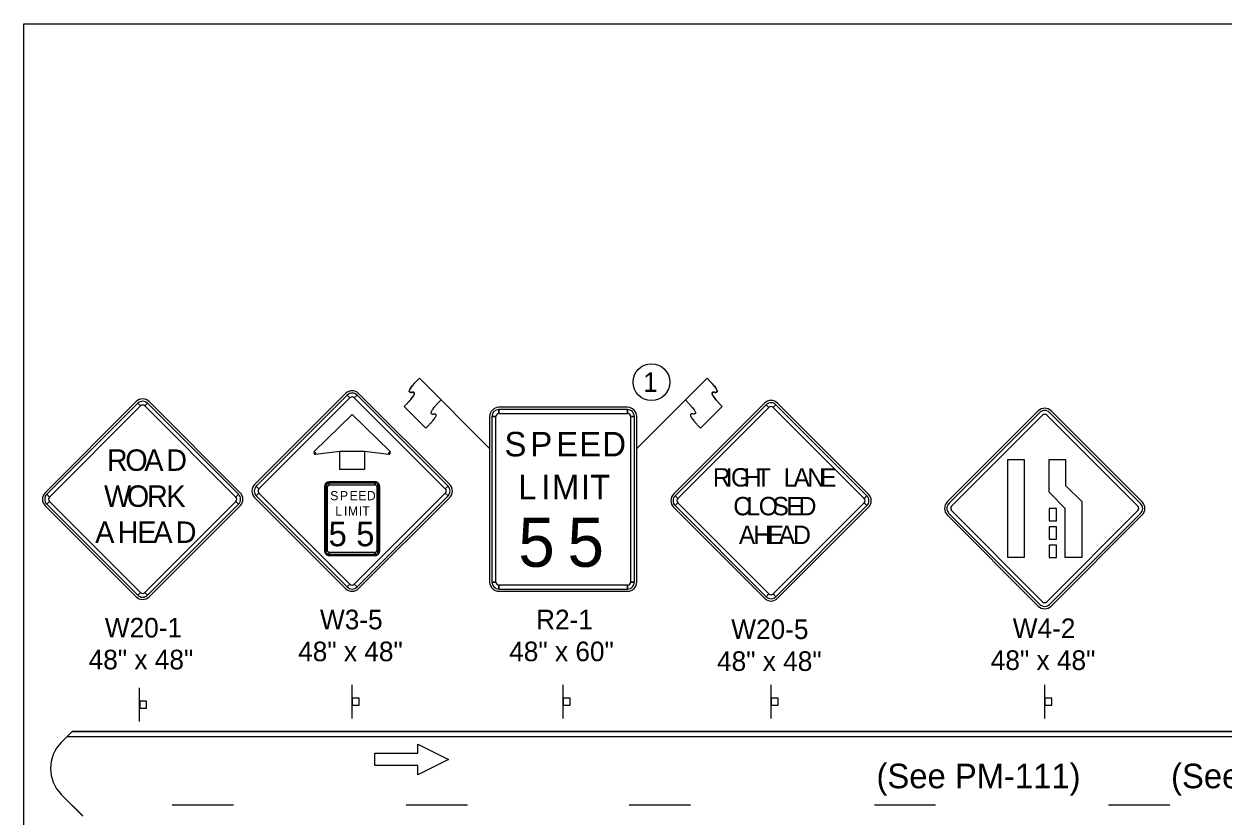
# Model space of a CAD drawing. Extents: x 10133 to 2270741, y 5363 to 1733450.
# Drawn here: x 28133 to 29111, y 9298 to 9944 of the extents above; entities that cross this region are included whole.
import ezdxf

# ---------------------------------------------------------------- set-up
doc = ezdxf.new("R2010")
doc.units = 0
for name, color, linetype in [('dsnNonPlotable', 7, 'Continuous'), ('dsnShtPlotShapeBatchPrint', 7, 'Continuous'), ('dsnStdBorder', 7, 'Continuous'), ('Level 2', 7, 'Continuous'), ('SheetBorder', 7, 'Continuous'), ('SheetText', 7, 'Continuous')]:
    doc.layers.add(name, color=color, linetype=linetype)

msp = doc.modelspace()

# ---------------------------------------------------------------- linework, layer by layer
at = {"layer": 'dsnNonPlotable'}
for p, q in [((28171.75, 9367.06), (28162.96, 9358.27)), ((28162.96, 9315.85), (28180.53, 9298.29))]:
    msp.add_line(p, q, dxfattribs=at)
msp.add_lwpolyline([(28167.75, 9363.06), (30246.68, 9363.06)], dxfattribs=at)
msp.add_arc((28184.17, 9337.07), 30, 135, 225, dxfattribs=at)
at = {"layer": 'dsnShtPlotShapeBatchPrint'}
msp.add_circle((28644.37, 9652.02), 15, dxfattribs=at)
at = {"layer": 'dsnStdBorder'}
for p, q in [((28512.42, 9597.93), (28455.1, 9655.24)), ((28455.1, 9655.24), (28472.79, 9637.56)), ((28632.42, 9597.93), (28689.74, 9655.24)), ((28689.74, 9655.24), (28672.06, 9637.56)), ((28224.04, 9636.12), (28149.79, 9561.87)), ((28308.89, 9561.87), (28234.64, 9636.12)), ((28394.94, 9642.77), (28320.7, 9568.53)), ((28396.27, 9641.45), (28398.48, 9639.24)), ((28402.02, 9639.24), (28404.23, 9641.45)), ((28479.8, 9568.53), (28405.55, 9642.77)), ((28225.36, 9634.8), (28227.57, 9632.59)), ((28231.11, 9632.59), (28233.32, 9634.8)), ((28442.73, 9632.25), (28460.4, 9614.57)), ((28460.4, 9614.57), (28442.73, 9632.25)), ((28624.92, 9631.48), (28519.92, 9631.48)), ((28519.92, 9626.48), (28519.92, 9629.6)), ((28624.92, 9629.6), (28624.92, 9626.48)), ((28736.67, 9634.87), (28662.42, 9560.62)), ((28702.12, 9632.25), (28684.44, 9614.57)), ((28684.44, 9614.57), (28702.12, 9632.25)), ((28737.99, 9633.54), (28740.2, 9631.33)), ((28743.74, 9631.33), (28745.95, 9633.54)), ((28821.52, 9560.62), (28747.27, 9634.87)), ((28959.97, 9628.56), (28885.72, 9554.31)), ((28885.72, 9554.31), (28959.97, 9628.56)), ((28961.3, 9627.23), (28887.05, 9552.99)), ((29043.5, 9552.99), (28969.25, 9627.23)), ((29044.83, 9554.31), (28970.58, 9628.56)), ((28970.58, 9628.56), (29044.83, 9554.31)), ((28970.58, 9628.56), (28970.58, 9628.56)), ((28512.42, 9623.98), (28512.42, 9488.98)), ((28514.3, 9623.98), (28517.42, 9623.98)), ((28627.42, 9623.98), (28630.55, 9623.98)), ((28632.42, 9488.98), (28632.42, 9623.98)), ((28889.26, 9550.78), (28963.51, 9625.02)), ((28967.04, 9625.02), (28967.04, 9625.03)), ((28967.04, 9625.02), (29041.29, 9550.78)), ((28370.25, 9594.47), (28369.36, 9595.36)), ((28370.4, 9593.23), (28370.25, 9594.47)), ((28430.25, 9594.47), (28430.09, 9593.23)), ((28431.13, 9595.36), (28430.25, 9594.47)), ((28324.23, 9564.99), (28322.02, 9567.2)), ((28377.75, 9566.97), (28377.75, 9514.47)), ((28378.69, 9566.97), (28380.25, 9566.97)), ((28419, 9570.72), (28381.5, 9570.72)), ((28381.5, 9568.22), (28381.5, 9569.78)), ((28419, 9569.78), (28419, 9568.22)), ((28420.25, 9566.97), (28421.81, 9566.97)), ((28422.75, 9514.47), (28422.75, 9566.97)), ((28478.47, 9567.2), (28476.26, 9564.99)), ((28153.33, 9558.34), (28151.12, 9560.55)), ((28307.56, 9560.55), (28305.36, 9558.34)), ((28320.7, 9557.92), (28394.94, 9483.67)), ((28322.02, 9559.24), (28324.23, 9561.45)), ((28405.55, 9483.67), (28479.8, 9557.92)), ((28476.26, 9561.45), (28478.47, 9559.24)), ((28665.96, 9557.08), (28663.75, 9559.29)), ((28820.19, 9559.29), (28817.98, 9557.08)), ((28149.79, 9551.27), (28224.04, 9477.02)), ((28151.12, 9552.59), (28153.33, 9554.8)), ((28234.64, 9477.02), (28308.89, 9551.27)), ((28305.36, 9554.8), (28307.56, 9552.59)), ((28662.42, 9550.01), (28736.67, 9475.77)), ((28663.75, 9551.34), (28665.96, 9553.55)), ((28747.27, 9475.77), (28821.52, 9550.01)), ((28817.98, 9553.55), (28820.19, 9551.34)), ((28963.51, 9472.99), (28889.26, 9547.24)), ((29041.29, 9547.24), (28967.04, 9472.99)), ((28885.72, 9543.71), (28959.97, 9469.46)), ((28959.97, 9469.46), (28885.72, 9543.71)), ((28887.05, 9545.03), (28961.3, 9470.78)), ((28969.25, 9470.78), (29043.5, 9545.03)), ((28970.58, 9469.46), (29044.83, 9543.71)), ((29044.83, 9543.71), (28970.58, 9469.46)), ((28380.25, 9514.47), (28378.69, 9514.47)), ((28381.5, 9511.66), (28381.5, 9513.22)), ((28381.5, 9510.72), (28419, 9510.72)), ((28419, 9513.22), (28419, 9511.66)), ((28421.81, 9514.47), (28420.25, 9514.47)), ((28517.42, 9488.98), (28514.3, 9488.98)), ((28630.55, 9488.98), (28627.42, 9488.98)), ((28227.57, 9480.56), (28225.36, 9478.35)), ((28233.32, 9478.35), (28231.11, 9480.56)), ((28398.48, 9487.21), (28396.27, 9485)), ((28404.23, 9485), (28402.02, 9487.21)), ((28519.92, 9483.35), (28519.92, 9486.48)), ((28519.92, 9481.48), (28624.92, 9481.48)), ((28624.92, 9486.48), (28624.92, 9483.35)), ((28740.2, 9479.3), (28737.99, 9477.09)), ((28745.95, 9477.09), (28743.74, 9479.3))]:
    msp.add_line(p, q, dxfattribs=at)
for points in [[(28396.27, 9641.45), (28322.02, 9567.2), (28324.23, 9564.99), (28398.48, 9639.24), (28396.27, 9641.45)], [(28478.47, 9567.2), (28404.23, 9641.45), (28402.02, 9639.24), (28476.26, 9564.99), (28478.47, 9567.2)], [(28225.36, 9634.8), (28151.12, 9560.55), (28153.33, 9558.34), (28227.57, 9632.59), (28225.36, 9634.8)], [(28307.56, 9560.55), (28233.32, 9634.8), (28231.11, 9632.59), (28305.36, 9558.34), (28307.56, 9560.55)], [(28400.25, 9625.72), (28369.36, 9595.36), (28370.25, 9594.47), (28370.4, 9593.23), (28390.25, 9595.72), (28410.25, 9595.72), (28430.09, 9593.23), (28430.25, 9594.47), (28431.13, 9595.36), (28400.25, 9625.72)], [(28624.92, 9629.6), (28519.92, 9629.6), (28519.92, 9626.48), (28624.92, 9626.48), (28624.92, 9629.6)], [(28737.99, 9633.54), (28663.75, 9559.29), (28665.96, 9557.08), (28740.2, 9631.33), (28737.99, 9633.54)], [(28820.19, 9559.29), (28745.95, 9633.54), (28743.74, 9631.33), (28817.98, 9557.08), (28820.19, 9559.29)], [(28514.3, 9623.98), (28514.3, 9488.98), (28517.42, 9488.98), (28517.42, 9623.98), (28514.3, 9623.98)], [(28630.55, 9488.98), (28630.55, 9623.98), (28627.42, 9623.98), (28627.42, 9488.98), (28630.55, 9488.98)], [(28410.25, 9580.72), (28390.25, 9580.72), (28390.25, 9595.72), (28410.25, 9595.72), (28410.25, 9580.72)], [(28948.52, 9589.01), (28948.52, 9509.01), (28935.02, 9509.01), (28935.02, 9589.01)], [(28982.28, 9567.85), (28995.53, 9554.6), (28995.53, 9509.01), (28982.03, 9509.01), (28982.03, 9549.01), (28968.78, 9562.26), (28968.78, 9589.01), (28982.28, 9589.01)], [(28378.69, 9566.97), (28378.69, 9514.47), (28380.25, 9514.47), (28380.25, 9566.97), (28378.69, 9566.97)], [(28419, 9569.78), (28381.5, 9569.78), (28381.5, 9568.22), (28419, 9568.22), (28419, 9569.78)], [(28421.81, 9514.47), (28421.81, 9566.97), (28420.25, 9566.97), (28420.25, 9514.47), (28421.81, 9514.47)], [(28322.02, 9559.24), (28396.27, 9485), (28398.48, 9487.21), (28324.23, 9561.45), (28322.02, 9559.24)], [(28404.23, 9485), (28478.47, 9559.24), (28476.26, 9561.45), (28402.02, 9487.21), (28404.23, 9485)], [(28151.12, 9552.59), (28225.36, 9478.35), (28227.57, 9480.56), (28153.33, 9554.8), (28151.12, 9552.59)], [(28233.32, 9478.35), (28307.56, 9552.59), (28305.36, 9554.8), (28231.11, 9480.56), (28233.32, 9478.35)], [(28663.75, 9551.34), (28737.99, 9477.09), (28740.2, 9479.3), (28665.96, 9553.55), (28663.75, 9551.34)], [(28745.95, 9477.09), (28820.19, 9551.34), (28817.98, 9553.55), (28743.74, 9479.3), (28745.95, 9477.09)], [(28974.78, 9549.01), (28968.78, 9549.01), (28968.78, 9539.01), (28974.78, 9539.01)], [(28974.78, 9534.01), (28968.78, 9534.01), (28968.78, 9524.01), (28974.78, 9524.01)], [(28974.78, 9519.01), (28968.78, 9519.01), (28968.78, 9509.01), (28974.78, 9509.01)], [(28381.5, 9511.66), (28419, 9511.66), (28419, 9513.22), (28381.5, 9513.22), (28381.5, 9511.66)], [(28519.92, 9483.35), (28624.92, 9483.35), (28624.92, 9486.48), (28519.92, 9486.48), (28519.92, 9483.35)]]:
    msp.add_lwpolyline(points, close=True, dxfattribs=at)
for points in [[(28887.05, 9552.99), (28961.3, 9627.23)], [(28969.25, 9627.23), (29043.5, 9552.99)], [(28889.26, 9550.78), (28963.51, 9625.03)], [(28967.04, 9625.03), (29041.29, 9550.78)], [(28963.51, 9472.99), (28889.26, 9547.24)], [(29041.29, 9547.24), (28967.04, 9472.99)], [(28961.3, 9470.78), (28887.05, 9545.03)], [(29043.5, 9545.03), (28969.25, 9470.78)]]:
    msp.add_lwpolyline(points, dxfattribs=at)
for centre, radius, start, end in [((28400.25, 9637.47), 7.5, 44.99999, 134.99974), ((28229.34, 9630.82), 7.5, 44.99999, 134.99974), ((28229.34, 9630.82), 5.62, 44.99999, 134.99974), ((28400.25, 9637.47), 5.62, 44.99999, 134.99974), ((28400.25, 9637.47), 2.5, 44.99999, 134.99974), ((28741.97, 9629.56), 7.5, 44.99999, 134.99974), ((28741.97, 9629.56), 5.62, 44.99999, 134.99974), ((28229.34, 9630.82), 2.5, 44.99999, 134.99974), ((28519.92, 9623.98), 7.5, 90.00021, 179.99985), ((28519.92, 9623.98), 5.62, 90.00021, 179.99985), ((28519.92, 9623.98), 2.5, 90.00021, 179.99985), ((28624.92, 9623.98), 7.5, 0, 90.00021), ((28624.92, 9623.98), 5.62, 0, 90.00021), ((28624.92, 9623.98), 2.5, 0, 90.00021), ((28741.97, 9629.56), 2.5, 44.99999, 134.99974), ((28965.28, 9623.26), 7.5, 44.99999, 134.99974), ((28965.28, 9623.26), 7.5, 44.99999, 134.99974), ((28965.28, 9623.26), 5.63, 44.99999, 134.99974), ((28965.28, 9623.26), 5.63, 44.99999, 134.99974), ((28965.28, 9623.26), 2.5, 44.99999, 134.99974), ((28965.28, 9623.26), 2.5, 44.99999, 134.99974), ((28370.25, 9594.47), 1.25, 134.99974, 277.15286), ((28430.25, 9594.47), 1.25, 262.84725, 44.9998), ((28326, 9563.22), 7.5, 134.99974, 224.99995), ((28326, 9563.22), 5.62, 134.99974, 224.99995), ((28381.5, 9566.97), 3.75, 90.00021, 179.99985), ((28381.5, 9566.97), 2.81, 90.00021, 179.99985), ((28381.5, 9566.97), 1.25, 90.00021, 179.99985), ((28419, 9566.97), 3.75, 0, 90.00021), ((28419, 9566.97), 2.81, 0, 90.00021), ((28419, 9566.97), 1.25, 0, 90.00021), ((28474.49, 9563.22), 5.62, 315.00016, 44.9998), ((28474.49, 9563.22), 7.5, 315.00016, 44.9998), ((28155.1, 9556.57), 7.5, 134.99974, 224.99995), ((28155.1, 9556.57), 5.62, 134.99974, 224.99995), ((28155.1, 9556.57), 2.5, 134.99974, 224.99995), ((28303.59, 9556.57), 2.5, 315.00016, 44.9998), ((28303.59, 9556.57), 5.62, 315.00016, 44.9998), ((28303.59, 9556.57), 7.5, 315.00016, 44.9998), ((28326, 9563.22), 2.5, 134.99974, 224.99995), ((28474.49, 9563.22), 2.5, 315.00016, 44.9998), ((28667.72, 9555.32), 7.5, 134.99974, 224.99995), ((28667.72, 9555.32), 5.62, 134.99974, 224.99995), ((28667.72, 9555.32), 2.5, 134.99974, 224.99995), ((28816.22, 9555.32), 2.5, 315.00016, 44.9998), ((28816.22, 9555.32), 5.62, 315.00016, 44.9998), ((28816.22, 9555.32), 7.5, 315.00016, 44.9998), ((28891.03, 9549.01), 7.5, 134.99974, 224.99995), ((28891.03, 9549.01), 7.5, 134.99974, 224.99995), ((28891.03, 9549.01), 5.63, 134.99974, 224.99995), ((28891.03, 9549.01), 5.63, 134.99974, 224.99995), ((28891.03, 9549.01), 2.5, 134.99974, 224.99995), ((28891.03, 9549.01), 2.5, 134.99974, 224.99995), ((29039.52, 9549.01), 2.5, 315.00016, 44.9998), ((29039.52, 9549.01), 2.5, 315.00016, 44.9998), ((29039.52, 9549.01), 5.63, 315.00016, 44.9998), ((29039.52, 9549.01), 5.63, 315.00016, 44.9998), ((29039.52, 9549.01), 7.5, 315.00016, 44.9998), ((29039.52, 9549.01), 7.5, 315.00016, 44.9998), ((28381.5, 9514.47), 3.75, 179.99985, 270.00006), ((28381.5, 9514.47), 2.81, 179.99985, 270.00006), ((28381.5, 9514.47), 1.25, 179.99985, 270.00006), ((28419, 9514.47), 3.75, 270.00006, 0.00027), ((28419, 9514.47), 2.81, 270.00006, 0.00027), ((28419, 9514.47), 1.25, 270.00006, 0.00027), ((28519.92, 9488.98), 7.5, 179.99985, 270.00006), ((28519.92, 9488.98), 5.62, 179.99985, 270.00006), ((28519.92, 9488.98), 2.5, 179.99985, 270.00006), ((28624.92, 9488.98), 7.5, 270.00006, 0.00027), ((28624.92, 9488.98), 5.62, 270.00006, 0.00027), ((28624.92, 9488.98), 2.5, 270.00006, 0.00027), ((28229.34, 9482.33), 2.5, 224.99995, 315.00016), ((28400.25, 9488.98), 7.5, 224.99995, 315.00016), ((28400.25, 9488.98), 5.62, 224.99995, 315.00016), ((28400.25, 9488.98), 2.5, 224.99995, 315.00016), ((28741.97, 9481.07), 2.5, 224.99995, 315.00016), ((28229.34, 9482.33), 7.5, 224.99995, 315.00016), ((28229.34, 9482.33), 5.62, 224.99995, 315.00016), ((28741.97, 9481.07), 7.5, 224.99995, 315.00016), ((28741.97, 9481.07), 5.62, 224.99995, 315.00016), ((28965.28, 9474.76), 7.5, 224.99995, 315.00016), ((28965.28, 9474.76), 7.5, 224.99995, 315.00016), ((28965.28, 9474.76), 5.63, 224.99995, 315.00016), ((28965.28, 9474.76), 5.63, 224.99995, 315.00016), ((28965.28, 9474.76), 2.5, 224.99995, 315.00016), ((28965.28, 9474.76), 2.5, 224.99995, 315.00016)]:
    msp.add_arc(centre, radius, start, end, dxfattribs=at)
for points in [[(28455.1, 9655.24), (28442.73, 9642.86), (28455.1, 9644.63), (28442.73, 9632.25)], [(28442.73, 9632.25), (28455.1, 9644.63), (28442.73, 9642.86), (28455.1, 9655.24)], [(28689.74, 9655.24), (28702.12, 9642.86), (28689.74, 9644.63), (28702.12, 9632.25)], [(28702.12, 9632.25), (28689.74, 9644.63), (28702.12, 9642.86), (28689.74, 9655.24)], [(28472.79, 9637.56), (28460.41, 9625.18), (28472.78, 9626.95), (28460.4, 9614.57)], [(28472.79, 9637.56), (28460.41, 9625.18), (28472.78, 9626.95), (28460.4, 9614.57)], [(28672.06, 9637.56), (28684.44, 9625.18), (28672.07, 9626.95), (28684.44, 9614.57)], [(28672.06, 9637.56), (28684.44, 9625.18), (28672.07, 9626.95), (28684.44, 9614.57)]]:
    msp.add_open_spline(points, degree=2, dxfattribs=at)
at = {"layer": 'Level 2'}
for p, q in [((28162.96, 9358.28), (28167.75, 9363.06)), ((28171.75, 9367.06), (28167.75, 9363.06)), ((28167.75, 9363.06), (29348.98, 9363.06)), ((28167.75, 9363.06), (29927.31, 9363.06)), ((28171.75, 9367.06), (30262.36, 9367.06)), ((29925.59, 9367.06), (28171.75, 9367.06)), ((28180.53, 9298.28), (28162.96, 9315.86))]:
    msp.add_line(p, q, dxfattribs=at)
msp.add_lwpolyline([(28167.75, 9363.06), (28167.75, 9363.06)], dxfattribs=at)
msp.add_lwpolyline([(28167.75, 9363.06), (28167.75, 9363.06)], dxfattribs=at)
msp.add_arc((28184.17, 9337.07), 30, 135, 225, dxfattribs=at)
at = {"layer": 'SheetBorder'}
msp.add_lwpolyline([(28132.52, 9944.02), (31267.53, 9944.02), (31267.53, 7924.02), (28132.52, 7924.02)], close=True, dxfattribs=at)
at = {"layer": 'SheetText'}
for p, q in [((28226.85, 9375.33), (28226.85, 9402.83)), ((28400.25, 9377.85), (28400.25, 9405.35)), ((28572.42, 9377.85), (28572.42, 9405.35)), ((28741.97, 9377.85), (28741.97, 9405.35)), ((28965.28, 9377.85), (28965.28, 9405.35))]:
    msp.add_line(p, q, dxfattribs=at)
for points in [[(28226.94, 9391.78), (28226.94, 9386.15), (28232.57, 9386.15), (28232.57, 9391.78)], [(28400.34, 9394.3), (28400.34, 9388.68), (28405.97, 9388.68), (28405.97, 9394.3)], [(28572.52, 9394.3), (28572.52, 9388.68), (28578.14, 9388.68), (28578.14, 9394.3)], [(28742.07, 9394.3), (28742.07, 9388.68), (28747.69, 9388.68), (28747.69, 9394.3)], [(28965.37, 9394.3), (28965.37, 9388.68), (28971, 9388.68), (28971, 9394.3)]]:
    msp.add_lwpolyline(points, close=True, dxfattribs=at)
for points in [[(28418.82, 9339.39), (28418.82, 9349.39), (28453.82, 9349.39), (28453.82, 9356.89), (28478.82, 9344.39), (28453.82, 9331.89), (28453.82, 9339.39), (28418.82, 9339.39)], [(28253.34, 9307.46), (28303.33, 9307.46)], [(28444.31, 9307.46), (28494.3, 9307.46)], [(28626.28, 9307.46), (28676.27, 9307.46)], [(28826.25, 9307.46), (28876.24, 9307.46)], [(29017.21, 9307.46), (29067.21, 9307.46)]]:
    msp.add_lwpolyline(points, dxfattribs=at)

# ---------------------------------------------------------------- texts
at = {"layer": 'dsnShtPlotShapeBatchPrint'}
msp.add_text('1', height=16, dxfattribs=at).set_placement((28637.67, 9644.02))
at = {"layer": 'dsnStdBorder'}
for s, height, p in [('S', 20, (28524.55, 9591.48)), ('P', 20, (28545.65, 9591.48)), ('E', 20, (28566.74, 9591.48)), ('E', 20, (28585.55, 9591.48)), ('D', 20, (28604.36, 9591.48)), ('R', 17.5, (28200.18, 9579.7)), ('O', 17.5, (28215.19, 9579.7)), ('A', 17.5, (28230.74, 9579.7)), ('D', 17.5, (28248.62, 9579.7)), ('L', 20, (28535.8, 9556.48)), ('I', 20, (28554.61, 9556.48)), ('M', 20, (28563.21, 9556.48)), ('I', 20, (28586.8, 9556.48)), ('T', 20, (28594.36, 9556.48)), ('R', 15, (28694.49, 9566.88)), ('I', 15, (28704.93, 9566.88)), ('G', 15, (28709.28, 9566.88)), ('H', 15, (28719.73, 9566.88)), ('T', 15, (28729.73, 9566.88)), ('L', 15, (28752.23, 9566.88)), ('A', 15, (28760.33, 9566.88)), ('N', 15, (28771.51, 9566.88)), ('E', 15, (28781.95, 9566.88)), ('W', 17.5, (28197.89, 9550.32)), ('O', 17.5, (28216.49, 9550.32)), ('R', 17.5, (28232.9, 9550.32)), ('K', 17.5, (28248.76, 9550.32)), ('S', 7.5, (28382.3, 9555.72)), ('P', 7.5, (28390.21, 9555.72)), ('E', 7.5, (28398.12, 9555.72)), ('E', 7.5, (28405.17, 9555.72)), ('D', 7.5, (28412.22, 9555.72)), ('C', 15, (28711.18, 9543.44)), ('L', 15, (28721.92, 9543.44)), ('O', 15, (28731.95, 9543.44)), ('S', 15, (28743.16, 9543.44)), ('E', 15, (28754.52, 9543.44)), ('D', 15, (28764.55, 9543.44)), ('L', 7.5, (28386.51, 9543.22)), ('I', 7.5, (28393.57, 9543.22)), ('M', 7.5, (28396.79, 9543.22)), ('I', 7.5, (28405.64, 9543.22)), ('T', 7.5, (28408.47, 9543.22)), ('A', 17.5, (28190.62, 9520.95)), ('H', 17.5, (28208.82, 9520.95)), ('E', 17.5, (28225.05, 9520.95)), ('A', 17.5, (28238.1, 9520.95)), ('D', 17.5, (28256.31, 9520.95)), ('5', 20, (28381, 9518.22)), ('5', 20, (28403.56, 9518.22)), ('5', 40, (28535.8, 9501.48)), ('5', 40, (28575.92, 9501.48)), ('A', 15, (28715.73, 9520)), ('H', 15, (28727.61, 9520)), ('E', 15, (28738.94, 9520)), ('A', 15, (28748.13, 9520)), ('D', 15, (28760.01, 9520)), ('W20-1', 16, (28198.49, 9443.83)), ('W3-5', 16, (28374, 9450.48)), ('R2-1', 16, (28550.26, 9450.48)), ('W4-2', 16, (28939.17, 9443.34)), ('W20-5', 16, (28709.51, 9442.57)), ('48" x 48"', 16, (28356.18, 9424.48)), ('48" x 60"', 16, (28528.36, 9424.48)), ('48" x 48"', 16, (28185.27, 9417.83)), ('48" x 48"', 16, (28697.9, 9416.57)), ('48" x 48"', 16, (28921.21, 9417.34)), ('(See PM-111)', 20, (28828.01, 9320.92)), ('(See PM-111)', 20, (29068.31, 9320.92))]:
    msp.add_text(s, height=height, dxfattribs=at).set_placement(p)

doc.saveas('drawing.dxf')
